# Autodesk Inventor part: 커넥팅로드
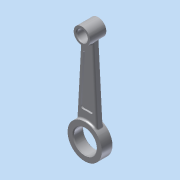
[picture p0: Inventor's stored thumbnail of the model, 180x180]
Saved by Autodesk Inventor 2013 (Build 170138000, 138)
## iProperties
Created: 2016-11
Part Number: 커넥팅로드
Material: 알루미늄 6061
Document SubType Name: Modeling
Designer: mduedu
Density: 2.71 g/cm^3
Mass: 64.7874 g
Surface Area: 114.14 cm^2
Volume: 23.9068 cm^3
Author: mduedu
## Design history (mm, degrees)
sketch "스케치1" dims "d0" = 42, "d3" = 20
  geometry: L1 (0, 0)-(0, 114); L2 (-7.5, 107.386)-(-12.5, 16.875); L3 (7.5, 107.386)-(12.5, 16.875); C1 r 14 at (0, 0); C2 r 6.5 at (0, 114); 3 further points
  constraints: 6 end point, 4 coincident, 2 centre point, 2 symmetric about line, 1 vertical, 6 other
  dimensions: "d1" = 28 diameter of C1; "d2" = 13 diameter of C2; "d4" = 114 distance of L1.start L1.end; "d6" = 12.5 distance from line of L1 L2.end; "d7" = 7.5 distance from line of L1 L2.start
extrude "돌출1" new body sketch "스케치1" stored distance "d8" = 13; taper "d9" = 0 deg
extrude "돌출2" join sketch "스케치1" stored distance "d10" = 20; taper "d11" = 0 deg
sketch "스케치2"
  geometry: L1 (-7.5, 107.386)-(-12.5, 16.875) reference; L2 (7.5, 107.386)-(12.5, 16.875) reference; A1 r 10 centre (0, 114) between (-7.5, 107.386) and (7.5, 107.386) reference; A2 r 21 centre (0, 0) between (-12.5, 16.875) and (12.5, 16.875) reference; 1 further point
extrude "돌출3" join sketch "스케치2" stored distance "d12" = 8; taper "d13" = 0 deg
sketch "스케치3"
  geometry: L1 (-7.5, 107.386)-(-12.5, 16.875) reference; L2 (7.5, 107.386)-(12.5, 16.875) reference; L3 (-4.209, 94.448)-(-7.768, 30.011); L4 (4.209, 94.448)-(7.768, 30.011); L5 (0, 94)-(0, 31); A1 r 10 centre (0, 114) between (-7.5, 107.386) and (7.5, 107.386) reference; A2 r 21 centre (0, 0) between (-12.5, 16.875) and (12.5, 16.875) reference; A3 r 20 centre (0, 114) between (-4.209, 94.448) and (4.209, 94.448); A4 r 31 centre (0, 0) between (7.768, 30.011) and (-7.768, 30.011); 1 further point
  constraints: 6 end point, 6 point on circle, 2 centre point, 2 parallel, 1 symmetric about line, 1 vertical alignment
  dimensions: "d18" = 10 radial gap between concentric circles of A3 A1; "d19" = 10 radial gap between concentric circles of A2 A4; "d20" = 4 distance between parallel lines of L3 L1
extrude "돌출4" cut sketch "스케치3" distance "d21" = 2; taper "d22" = 0 deg
fillet "모깎기1" dims "d23" = 3
fillet "모깎기2" dims "d24" = 2
fillet "모깎기3" dims "d25" = 2
chamfer "모따기1" distance "d26" = 1; stored, may be unused: second distance "d27" = 2, angle "d28" = 45 deg
node "솔리드1"
mirror "대칭1"
other parameters: "d16" = 4, "d17" = 4
